// Mitsubishi GX Works2 project: 27.浮点运算指令（加DE）   PLC: FX3U/FX3UC

PROGRAM MAIN
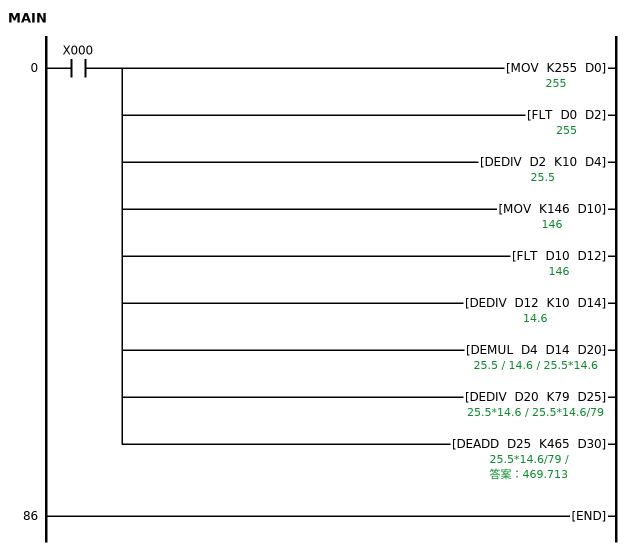
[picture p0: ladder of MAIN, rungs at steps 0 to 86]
0     LD      X000
      MOV     K255 D0  ; 255
      FLT     D0 D2
        [note] 把255存到D2D3
      DEDIV   D2 K10 D4  ; 25.5
        [note] 浮点运算必须加DE。255/10=25.5
      MOV     K146 D10  ; 146
      FLT     D10 D12
        [note] 把146存到D12D13
      DEDIV   D12 K10 D14  ; 14.6
        [note] 浮点运算必须加DE。146/10=14.6
      DEMUL   D4 D14 D20  ; 25.5*14.6
        [note] 浮点运算必须加DE。
      DEDIV   D20 K79 D25  ; 25.5*14.6/79
        [note] 浮点运算必须加DE。
      DEADD   D25 K465 D30  ; 答案：469.713
        [note] 浮点运算必须加DE。
86    END
END_PROGRAM
